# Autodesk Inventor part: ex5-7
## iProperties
Author: Administrator
Created: 2001-09
Part Number: ex5-7
Document SubType Name: Modeling
Designer: Administrator
Control State: 0
Master: False
Checked Out: False
PropertySet Name: Design Tracking Control
Length Units: 11272
Angle Units: 11279
Time Units: 11290
Mass Units: 11286
Shininess: 3
Angle Display Precision: 2
Document Length Units: 11272
Document Angle Units: 11286
Document Time Units: 11279
Document Mass Units: 11290
Document Length Units Precision: 3
Document Angle Units Precision: 2
Compacted: False
PropertySet Name: _Private Model Information
Density: 0.0
Volumn: 0.0
Area: 0.0
PropertySet Name: Model Information
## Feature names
1. Revolution1
2. Hole1
3. Shell1
4. Loft1
5. Sweep1
6. Coil1
